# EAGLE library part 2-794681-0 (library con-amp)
Micro MATE-N-LOK Connectors grid 1.5mm Dual Row Through Hole Vertical Metal Through Hole Holddowns Source: ENG_CD_794681_E.pdf
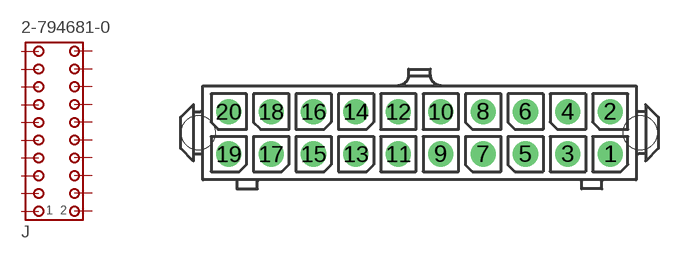
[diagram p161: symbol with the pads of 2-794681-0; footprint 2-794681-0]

Designator prefix J

## 2-794681-0 (MF: TYCO ELECTRONICS; MPN: 2-794681-0; OC_FARNELL: unknown; OC_NEWARK: 15H4199)  [2-794681-0]
1  1  pas
2  2  pas
3  3  pas
4  4  pas
5  5  pas
6  6  pas
7  7  pas
8  8  pas
9  9  pas
10  10  pas
11  11  pas
12  12  pas
13  13  pas
14  14  pas
15  15  pas
16  16  pas
17  17  pas
18  18  pas
19  19  pas
20  20  pas

## Footprint 2-794681-0 (pad centres in mm)
Micro MATE-N-LOK Connectors grid 1.5mm Dual Row Through Hole Vertical Metal Through Hole Holddowns Source: ENG_CD_794681_E.pdf
drill 1 pad 1.778 round: 1 13.5,-1.5; 2 13.5,1.5; 3 10.5,-1.5; 4 10.5,1.5; 5 7.5,-1.5; 6 7.5,1.5; 7 4.5,-1.5; 8 4.5,1.5; 9 1.5,-1.5; 10 1.5,1.5; 11 -1.5,-1.5; 12 -1.5,1.5; 13 -4.5,-1.5; 14 -4.5,1.5; 15 -7.5,-1.5; 16 -7.5,1.5; 17 -10.5,-1.5; 18 -10.5,1.5; 19 -13.5,-1.5; 20 -13.5,1.5
hole 2.4 at 15.63,0
hole 2.4 at -15.67,0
